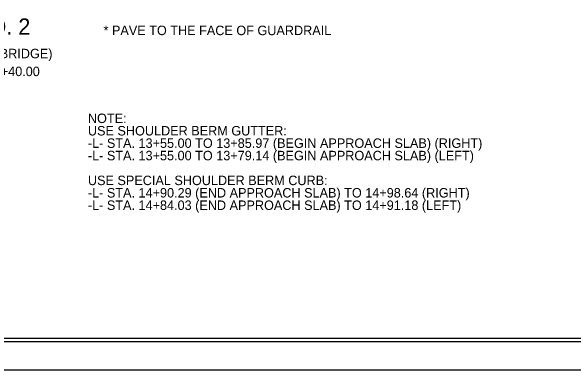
# Model space of a CAD drawing. Extents: x 1542177 to 1542464, y 45134 to 45344.
# Drawn here: x 1542284.79 to 1542320.47, y 45240.62 to 45263.33 of the extents above; entities that cross this region are included whole.
import ezdxf

# ---------------------------------------------------------------- set-up
doc = ezdxf.new("R2010")
doc.units = 0
for name, color, linetype in [('Default', 7, 'Continuous'), ('Sheet Cutting Line CELL', 7, 'Continuous'), ('Sheet Plot Border Inside CELL', 7, 'Continuous'), ('Sheet Plot Border Outside CELL', 7, 'Continuous'), ('Sheet Typical CELL', 7, 'Continuous')]:
    doc.layers.add(name, color=color, linetype=linetype)

msp = doc.modelspace()

# ---------------------------------------------------------------- linework, layer by layer
at = {"layer": 'Sheet Cutting Line CELL'}
msp.add_line((1542226.007, 45240.616), (1542360.727, 45240.616), dxfattribs=at)
at = {"layer": 'Sheet Plot Border Inside CELL'}
msp.add_lwpolyline([(1542360.367, 45326.82), (1542227.047, 45326.82), (1542227.047, 45242.412), (1542360.367, 45242.412)], close=True, dxfattribs=at)
at = {"layer": 'Sheet Plot Border Outside CELL'}
for points in [[(1542360.727, 45328.616), (1542226.007, 45328.616), (1542226.007, 45240.616), (1542360.727, 45240.616)], [(1542360.727, 45328.615), (1542226.007, 45328.615), (1542226.007, 45240.616), (1542360.727, 45240.616)]]:
    msp.add_lwpolyline(points, close=True, dxfattribs=at)
at = {"layer": 'Sheet Typical CELL'}
msp.add_lwpolyline([(1542359.367, 45326.616), (1542239.367, 45326.616), (1542239.367, 45242.616), (1542359.367, 45242.616)], close=True, dxfattribs=at)

# ---------------------------------------------------------------- texts
at = {"layer": 'Default'}
for s, height, p in [('TYPICAL SECTION NO. 2', 1.02627, (1542269.834, 45261.851)), ('* PAVE TO THE FACE OF GUARDRAIL', 0.6, (1542290.643, 45261.819)), ('-L- STA  12+90.00 TO -L- STA 13+93.84 (BEGIN BRIDGE)', 0.6, (1542266.358, 45260.354)), ('-L- STA  14+76.16 (END BRIDGE) TO -L- STA 15+40.00', 0.6, (1542266.358, 45259.221)), ('NOTE:', 0.6, (1542289.654, 45256.248)), ('USE SHOULDER BERM GUTTER:', 0.6, (1542289.654, 45255.461)), ('-L- STA. 13+55.00 TO 13+85.97 (BEGIN APPROACH SLAB) (RIGHT)', 0.6, (1542289.654, 45254.675)), ('-L- STA. 13+55.00 TO 13+79.14 (BEGIN APPROACH SLAB) (LEFT)', 0.6, (1542289.654, 45253.888)), ('USE SPECIAL SHOULDER BERM CURB:', 0.6, (1542289.654, 45252.315)), ('-L- STA. 14+90.29 (END APPROACH SLAB) TO 14+98.64 (RIGHT)', 0.6, (1542289.654, 45251.529)), ('-L- STA. 14+84.03 (END APPROACH SLAB) TO 14+91.18 (LEFT)', 0.6, (1542289.654, 45250.742))]:
    msp.add_text(s, height=height, dxfattribs=at).set_placement(p)

doc.saveas('drawing.dxf')
